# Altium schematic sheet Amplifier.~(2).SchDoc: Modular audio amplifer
size A3; Date: 15/07/2017; Author: Morgane Vallée; Organization: Altium Limited; Revision: 1.1; SheetNumber: 1; SheetTotal: 1
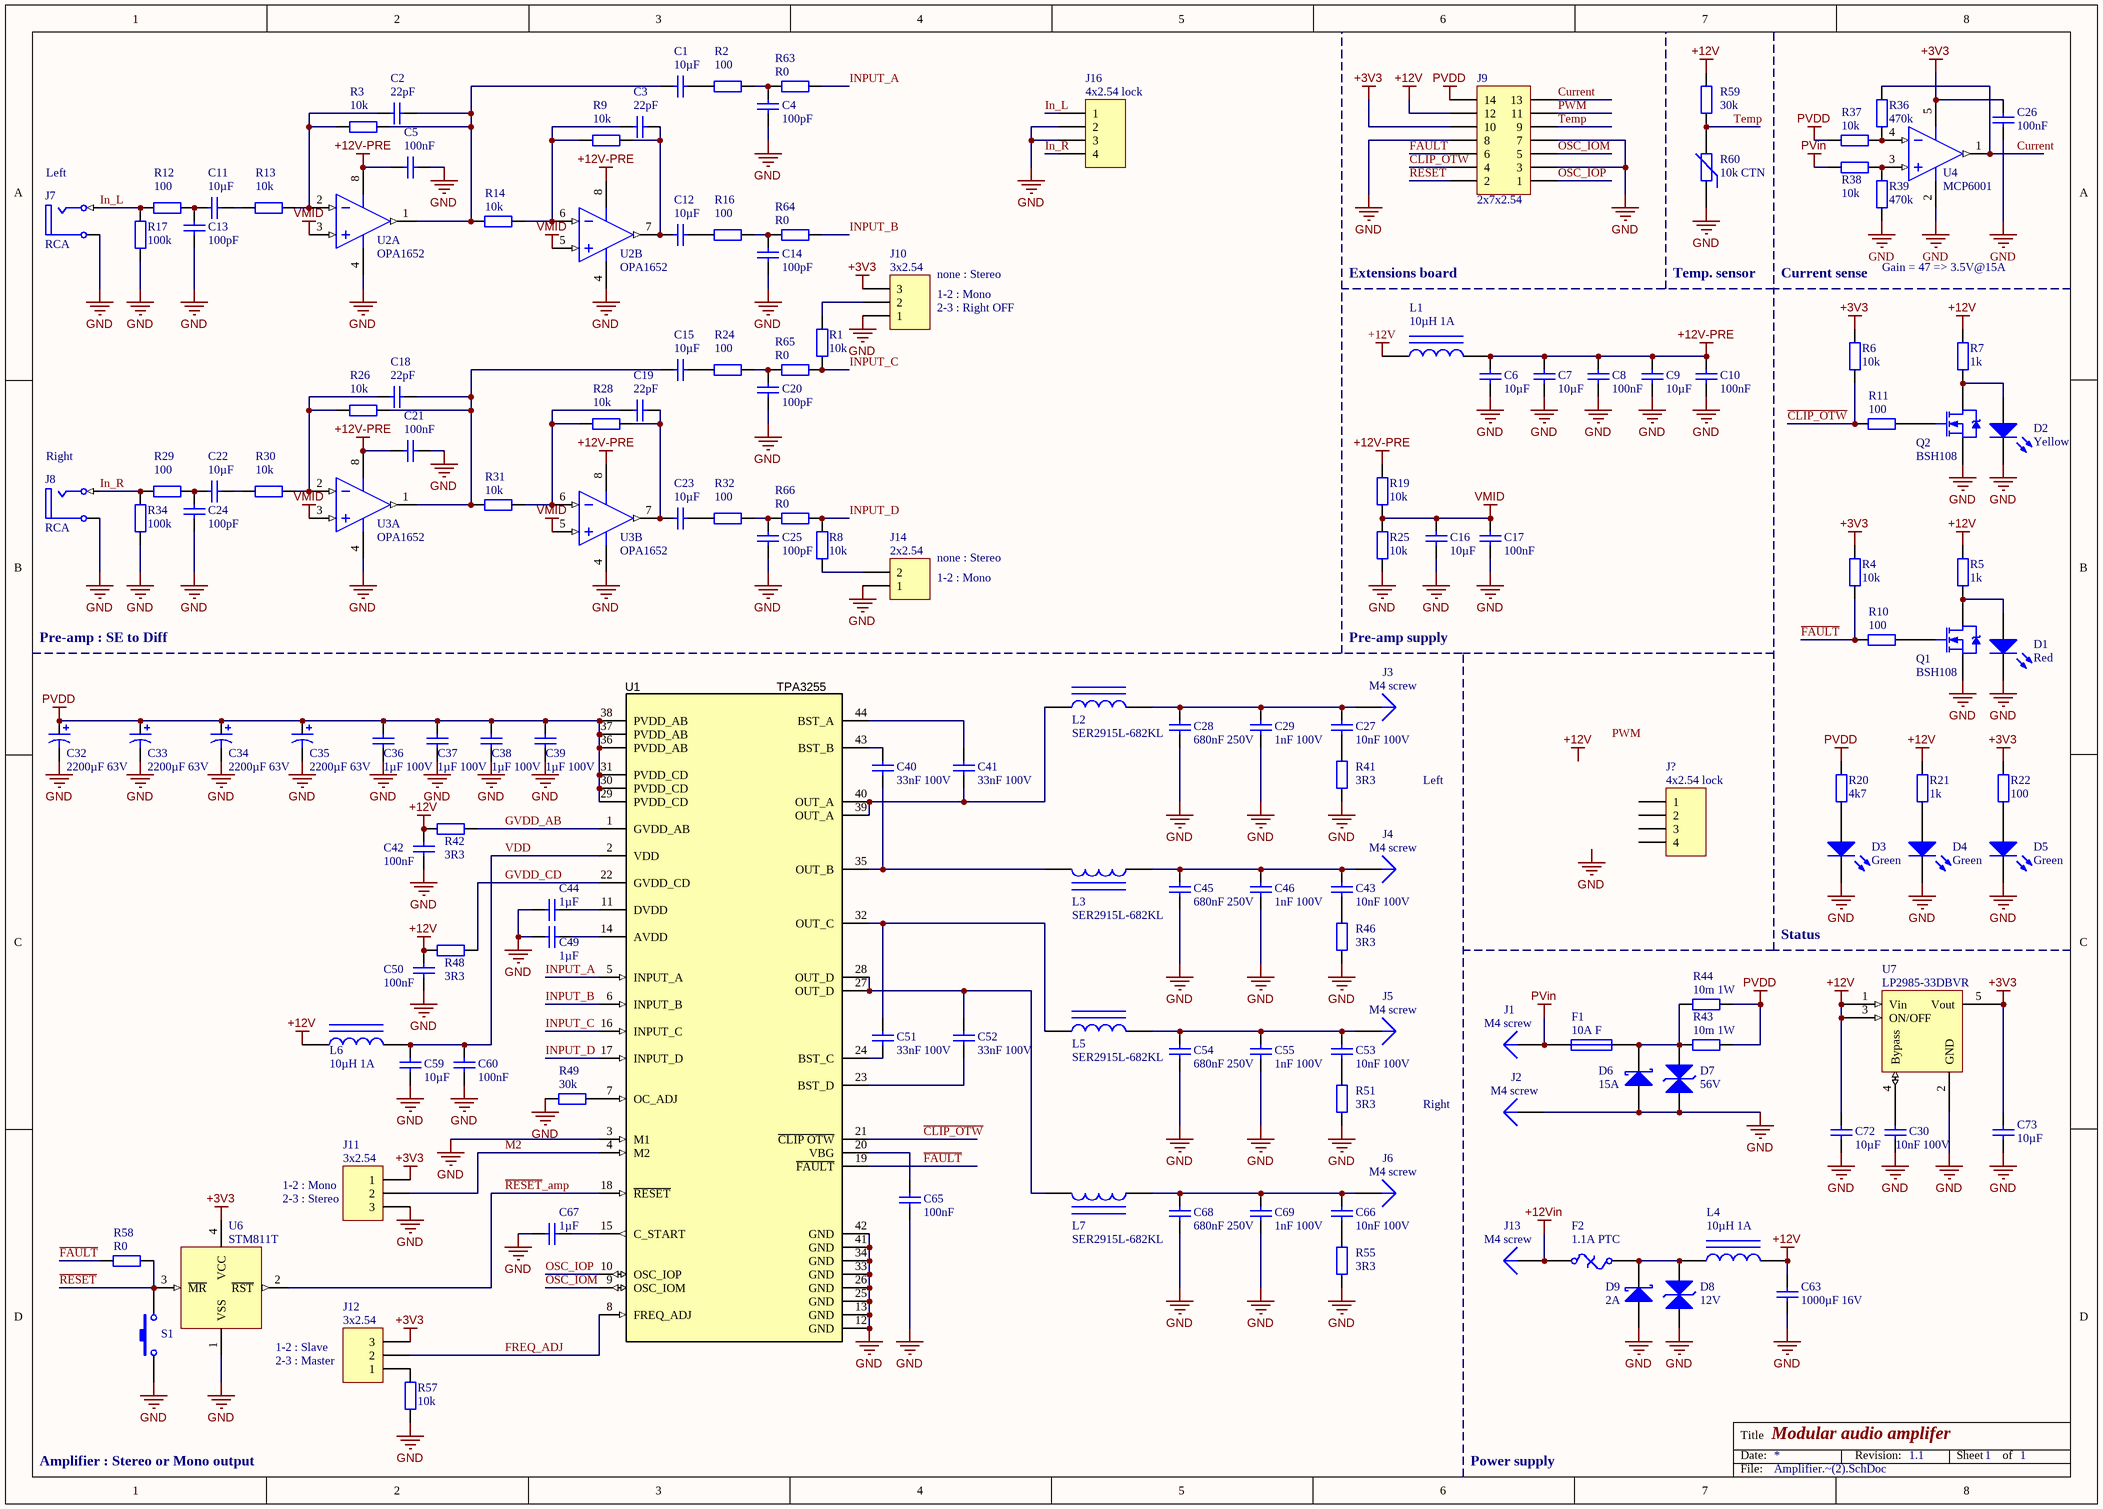
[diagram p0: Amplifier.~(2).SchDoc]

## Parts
C1  10µF  [C0805]
C2  22pF  [C0603]
C3  22pF  [C0603]
C4  100pF  [C0603]
C5  100nF  [C0603]
C6  10µF  [C0805]
C7  10µF  [C0805]
C8  100nF  [C0603]
C9  10µF  [C0805]
C10  100nF  [C0603]
C11  10µF  [C0805]
C12  10µF  [C0805]
C13  100pF  [C0603]
C14  100pF  [C0603]
C15  10µF  [C0805]
C16  10µF  [C0805]
C17  100nF  [C0603]
C18  22pF  [C0603]
C19  22pF  [C0603]
C20  100pF  [C0603]
C21  100nF  [C0603]
C22  10µF  [C0805]
C23  10µF  [C0805]
C24  100pF  [C0603]
C25  100pF  [C0603]
C26  100nF  [C0603]
C27  10nF 100V  [C0603]
C28  680nF 250V  [CAP_15]
C29  1nF 100V  [C0603]
C30  10nF 100V  [C0603]
C32  2200µF 63V  [CAP_18x7.5]
C33  2200µF 63V  [CAP_18x7.5]
C34  2200µF 63V  [CAP_18x7.5]
C35  2200µF 63V  [CAP_18x7.5]
C36  1µF 100V  [C1206]
C37  1µF 100V  [C1206]
C38  1µF 100V  [C1206]
C39  1µF 100V  [C1206]
C40  33nF 100V  [C0805]
C41  33nF 100V  [C0805]
C42  100nF  [C0603]
C43  10nF 100V  [C0603]
C44  1µF  [C0603]
C45  680nF 250V  [CAP_15]
C46  1nF 100V  [C0603]
C49  1µF  [C0603]
C50  100nF  [C0603]
C51  33nF 100V  [C0805]
C52  33nF 100V  [C0805]
C53  10nF 100V  [C0603]
C54  680nF 250V  [CAP_15]
C55  1nF 100V  [C0603]
C59  10µF  [C0805]
C60  100nF  [C0603]
C63  1000µF 16V  [CAP_10x5]
C65  100nF  [C0603]
C66  10nF 100V  [C0603]
C67  1µF  [C0603]
C68  680nF 250V  [CAP_15]
C69  1nF 100V  [C0603]
C72  10µF  [C0805]
C73  10µF  [C0805]
D1  Red  [C0603]
D2  Yellow  [C0603]
D3  Green  [C0603]
D4  Green  [C0603]
D5  Green  [C0603]
D6  15A  [DPAK]
D7  56V  [DO-214AC]
D8  12V  [DO-214AC]
D9  2A  [DO-214AC]
F1  10A F  [Fuse older]
F2  1.1A PTC  [MC362xx]
J1  M4 screw  [HOLE_4]
J2  M4 screw  [HOLE_4]
J3  M4 screw  [HOLE_4]
J4  M4 screw  [HOLE_4]
J5  M4 screw  [HOLE_4]
J6  M4 screw  [HOLE_4]
J7  RCA  [CON_RCA]
J8  RCA  [CON_RCA]
J9  2x7x2.54  [CON_header_2x7]
J10  3x2.54  [HDR1X3]
J11  3x2.54  [HDR1X3]
J12  3x2.54  [HDR1X3]
J13  M4 screw  [HOLE_4]
J14  2x2.54  [HDR1X2]
J16  4x2.54 lock  [HDR1X4]
J?  4x2.54 lock  [HDR1X4]
L1  10µH 1A  [SELF_6.7x3]
L2  SER2915L-682KL  [SELF_SMD_SER2915x]
L3  SER2915L-682KL  [SELF_SMD_SER2915x]
L4  10µH 1A  [SELF_6.7x3]
L5  SER2915L-682KL  [SELF_SMD_SER2915x]
L6  10µH 1A  [SELF_6.7x3]
L7  SER2915L-682KL  [SELF_SMD_SER2915x]
Q1  BSH108  [SOT-23-GSD]
Q2  BSH108  [SOT-23-GSD]
R1  10k  [R0603]
R2  100  [R0603]
R3  10k  [R0603]
R4  10k  [R0603]
R5  1k  [R0603]
R6  10k  [R0603]
R7  1k  [R0603]
R8  10k  [R0603]
R9  10k  [R0603]
R10  100  [R0603]
R11  100  [R0603]
R12  100  [R0603]
R13  10k  [R0603]
R14  10k  [R0603]
R16  100  [R0603]
R17  100k  [R0603]
R19  10k  [R0603]
R20  4k7  [R0603]
R21  1k  [R0603]
R22  100  [R0603]
R24  100  [R0603]
R25  10k  [R0603]
R26  10k  [R0603]
R28  10k  [R0603]
R29  100  [R0603]
R30  10k  [R0603]
R31  10k  [R0603]
R32  100  [R0603]
R34  100k  [R0603]
R36  470k  [R0603]
R37  10k  [R0603]
R38  10k  [R0603]
R39  470k  [R0603]
R41  3R3  [R0603]
R42  3R3  [R0603]
R43  10m 1W  [R2512]
R44  10m 1W  [R2512]
R46  3R3  [R0603]
R48  3R3  [R0603]
R49  30k  [R0603]
R51  3R3  [R0603]
R55  3R3  [R0603]
R57  10k  [R0603]
R58  R0  [R1206]
R59  30k  [R0603]
R60  10k CTN  [R0603]
R63  R0  [R1206]
R64  R0  [R1206]
R65  R0  [R1206]
R66  R0  [R1206]
S1  SW-PB  [BP_PCB]  (value not drawn)
U1  TPA3255  [TSSOP-44]
U2  OPA1652  [SOIC-8]  (parts A,B of 2)
U3  OPA1652  [SOIC-8]  (parts A,B of 2)
U4  MCP6001  [SOT-23-5]
U6  STM811T  [SOT143-4]
U7  LP2985-33DBVR  [SOT-23-5]

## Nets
+3V3: C26.1 C73.1 J9.10 J10.3 J11.1 J12.3 R4.1 R6.1 R22.1 U4.5(V+) U6.4(VCC) U7.5(Vout)
+12V: C42.1 C50.1 C63.1 C72.1 J9.12 L1.1 L4.2 L6.1 R5.1 R7.1 R21.1 R42.2 R48.2 R59.1 U7.1(Vin) U7.3(ON/OFF)
+12V-PRE: C5.1 C6.1 C7.1 C8.1 C9.1 C10.1 C21.1 L1.2 R19.1 U2.8(V+) U3.8(V+)
+12Vin: F2.1 J13.1
GND: C4.2 C5.2 C6.2 C7.2 C8.2 C9.2 C10.2 C13.2 C14.2 C16.2 C17.2 C20.2 C21.2 C24.2 C25.2 C26.2 C28.2 C29.2 C30.2 C32.2 C33.2 C34.2 C35.2 C36.2 C37.2 C38.2 C39.2 C42.2 C44.1 C45.2 C46.2 C49.1 C50.2 C54.2 C55.2 C59.2 C60.2 C63.2 C65.2 C67.1 C68.2 C69.2 C72.2 C73.2 D1.2(K) D2.2(K) D3.2(K) D4.2(K) D5.2(K) D6.1(A) D7.A D8.A D9.1(A) J2.1 J7.1A(Ground) J8.1A(Ground) J9.3 J9.7 J9.8 J10.1 J11.3 J14.1 J16.2 J16.3 Q1.3(S) Q2.3(S) R17.2 R25.2 R34.2 R39.2 R41.2 R46.2 R49.1 R51.2 R55.2 R57.1 R60.1 S1.1 U1.3(M1) U1.12(GND) U1.13(GND) U1.25(GND) U1.26(GND) U1.33(GND) U1.34(GND) U1.41(GND) U1.42(GND) U2.4(V-) U3.4(V-) U4.2(V-) U6.1(VSS) U7.2(GND)
PVDD: C32.1 C33.1 C34.1 C35.1 C36.1 C37.1 C38.1 C39.1 J9.14 R20.1 R37.1 R43.2 R44.2 U1.29(PVDD_CD) U1.30(PVDD_CD) U1.31(PVDD_CD) U1.36(PVDD_AB) U1.37(PVDD_AB) U1.38(PVDD_AB)
PVin: F1.1 J1.1 R38.1
VMID: C16.1 C17.1 R19.2 R25.1 U2.3(IN+) U2.5(IN+) U3.3(IN+) U3.5(IN+)
~{CLIP_OTW}: J9.4 R6.2 R11.2 U1.21(~{CLIP_OTW})
Current: J9.13 R36.1 U4.1(OUT)
~{FAULT}: J9.6 R4.2 R10.2 R58.2 U1.19(~{FAULT})
FREQ_ADJ: J12.2 U1.8(FREQ_ADJ)
GVDD_AB: R42.1 U1.1(GVDD_AB)
GVDD_CD: R48.1 U1.22(GVDD_CD)
In_L: J7.2B(Signal) J16.1 R12.2 R17.1
In_R: J8.2B(Signal) J16.4 R29.2 R34.1
INPUT_A: R63.1 U1.5(INPUT_A)
INPUT_B: R64.1 U1.6(INPUT_B)
INPUT_C: R1.2 R65.1 U1.16(INPUT_C)
INPUT_D: R8.1 R66.1 U1.17(INPUT_D)
M2: J11.2 U1.4(M2)
OSC_IOM: J9.5 U1.9(OSC_IOM)
OSC_IOP: J9.1 U1.10(OSC_IOP)
PWM: J9.11
~{RESET}: J9.2 R58.1 S1.2 U6.3(~{MR})
~{RESET}_amp: U1.18(~{RESET}) U6.2(~{RST})
Temp: J9.9 R59.2 R60.2
VDD: C59.1 C60.1 L6.2 U1.2(VDD)
NetC1_1: C1.1 C2.2 R3.1 R14.2 U2.1(OUT)
NetC1_2: C1.2 R2.2
NetC2_1: C2.1 R3.2 R13.1 U2.2(IN-)
NetC3_1: C3.1 R9.2 R14.1 U2.6(IN-)
NetC3_2: C3.2 C12.1 R9.1 U2.7(OUT)
NetC4_1: C4.1 R2.1 R63.2
NetC11_1: C11.1 C13.1 R12.1
NetC11_2: C11.2 R13.2
NetC12_2: C12.2 R16.2
NetC14_1: C14.1 R16.1 R64.2
NetC15_1: C15.1 C18.2 R26.1 R31.2 U3.1(OUT)
NetC15_2: C15.2 R24.2
NetC18_1: C18.1 R26.2 R30.1 U3.2(IN-)
NetC19_1: C19.1 R28.2 R31.1 U3.6(IN-)
NetC19_2: C19.2 C23.1 R28.1 U3.7(OUT)
NetC20_1: C20.1 R24.1 R65.2
NetC22_1: C22.1 C24.1 R29.1
NetC22_2: C22.2 R30.2
NetC23_2: C23.2 R32.2
NetC25_1: C25.1 R32.1 R66.2
NetC27_1: C27.1 C28.1 C29.1 J3.1 L2.2
NetC27_2: C27.2 R41.1
NetC30_1: C30.1 U7.4(Bypass)
NetC40_1: C40.1 L3.2 U1.35(OUT_B)
NetC40_2: C40.2 U1.43(BST_B)
NetC41_1: C41.1 L2.1 U1.39(OUT_A) U1.40(OUT_A)
NetC41_2: C41.2 U1.44(BST_A)
NetC43_1: C43.1 C45.1 C46.1 J4.1 L3.1
NetC43_2: C43.2 R46.1
NetC44_2: C44.2 U1.11(DVDD)
NetC49_2: C49.2 U1.14(AVDD)
NetC51_1: C51.1 U1.24(BST_C)
NetC51_2: C51.2 L5.1 U1.32(OUT_C)
NetC52_1: C52.1 U1.23(BST_D)
NetC52_2: C52.2 L7.2 U1.27(OUT_D) U1.28(OUT_D)
NetC53_1: C53.1 C54.1 C55.1 J5.1 L5.2
NetC53_2: C53.2 R51.1
NetC65_1: C65.1 U1.20(VBG)
NetC66_1: C66.1 C68.1 C69.1 J6.1 L7.1
NetC66_2: C66.2 R55.1
NetC67_2: C67.2 U1.15(C_START)
NetD1_1: D1.1(A) Q1.2(D) R5.2
NetD2_1: D2.1(A) Q2.2(D) R7.2
NetD3_1: D3.1(A) R20.2
NetD4_1: D4.1(A) R21.2
NetD5_1: D5.1(A) R22.2
NetD6_2: D6.2(K) D7.K F1.2 R43.1 R44.1
NetD8_K: D8.K D9.2(K) F2.2 L4.1
NetJ10_2: J10.2 R1.1
NetJ12_1: J12.1 R57.2
NetJ14_2: J14.2 R8.2
NetQ1_1: Q1.1(G) R10.1
NetQ2_1: Q2.1(G) R11.1
NetR36_2: R36.2 R37.2 U4.4(IN-)
NetR38_2: R38.2 R39.1 U4.3(IN+)
NetR49_2: R49.2 U1.7(OC_ADJ)

Not connected (* = marked no-connect by the designer): J? 1 2 3 4

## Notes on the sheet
- (near J7) Left
- (near J10) 1-2 : Mono
- (near J10) 2-3 : Right OFF
- (near J10) none : Stereo
- Extensions board
- Temp. sensor
- Current sense
- Gain = 47 => 3.5V@15A
- (near J8) Right
- (near J14) 1-2 : Mono
- (near J14) none : Stereo
- Pre-amp : SE to Diff
- Pre-amp supply
- Left
- Status
- Right
- 1-2 : Mono
- 2-3 : Stereo
- (near U6) 1-2 : Slave
- 2-3 : Master
- Amplifier : Stereo or Mono output
- Power supply
- Labels drawn without touching a wire or pin: +12V, GND, PWM

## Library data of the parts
C1-C30 C36-C46 C49-C55 C59 C60 C63 C65-C69 C72 C73 = Cap: Capacitor
C32-C35 = Cap Pol1: Polarized Capacitor (Radial)
D1-D5 = LED2: Typical RED, GREEN, YELLOW, AMBER GaAs LED
D6 = D Schottky: Schottky Diode; pin to pad: 1>1+3
D7 D8 = Diode TVS: TVS diode; pin to pad: A>1 K>2
D9 = D Schottky: Schottky Diode
F1 = Fuse 1: Fuse
F2 = Fuse Thermal: Thermal Fuse
J1-J6 J13 = Plug
J7 J8 = RCA: RCA Phono Jack, Right Angle, Thru-Hole, Snap-In; pin to pad: 1A>1 2B>2
J9 = Header 7X2: Header, 7-Pin, Dual row
J10-J12 = Header 3: Header, 3-Pin
J14 = Header 2: Header, 2-Pin
J16 J? = Header 4: Header, 4-Pin
L1-L7 = Inductor Iron: Magnetic-Core Inductor
Q1 Q2 = NMOS-2: N-Channel Power MOSFET
R1-R14 R16 R17 R19-R22 R24-R26 R28-R32 R34 R36-R39 R41-R44 R46 R48 R49 R51 R55 R57-R59 R63-R66 = Res2: Resistor
R60 = Res Varistor: Varistor (Voltage-Sensitive Resistor)
S1 = SW-PB: Switch
U1 = TPA3251D2DDVR: 150W Stereo/300W MONO PurePath HD Analog-input Power Stage, DDV0044D
U2 U3 = OPA1652: Low Noise and Distortion, General-Purpose, FET-Input Audio Op Amps
U4 = Op Amp: FET Operational Amplifier
U6 = STM8xx: Voltage monitor
U7 = LP2985-x: 150mA, Low-Noise, 350mVdrop max, LDO voltage regulator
